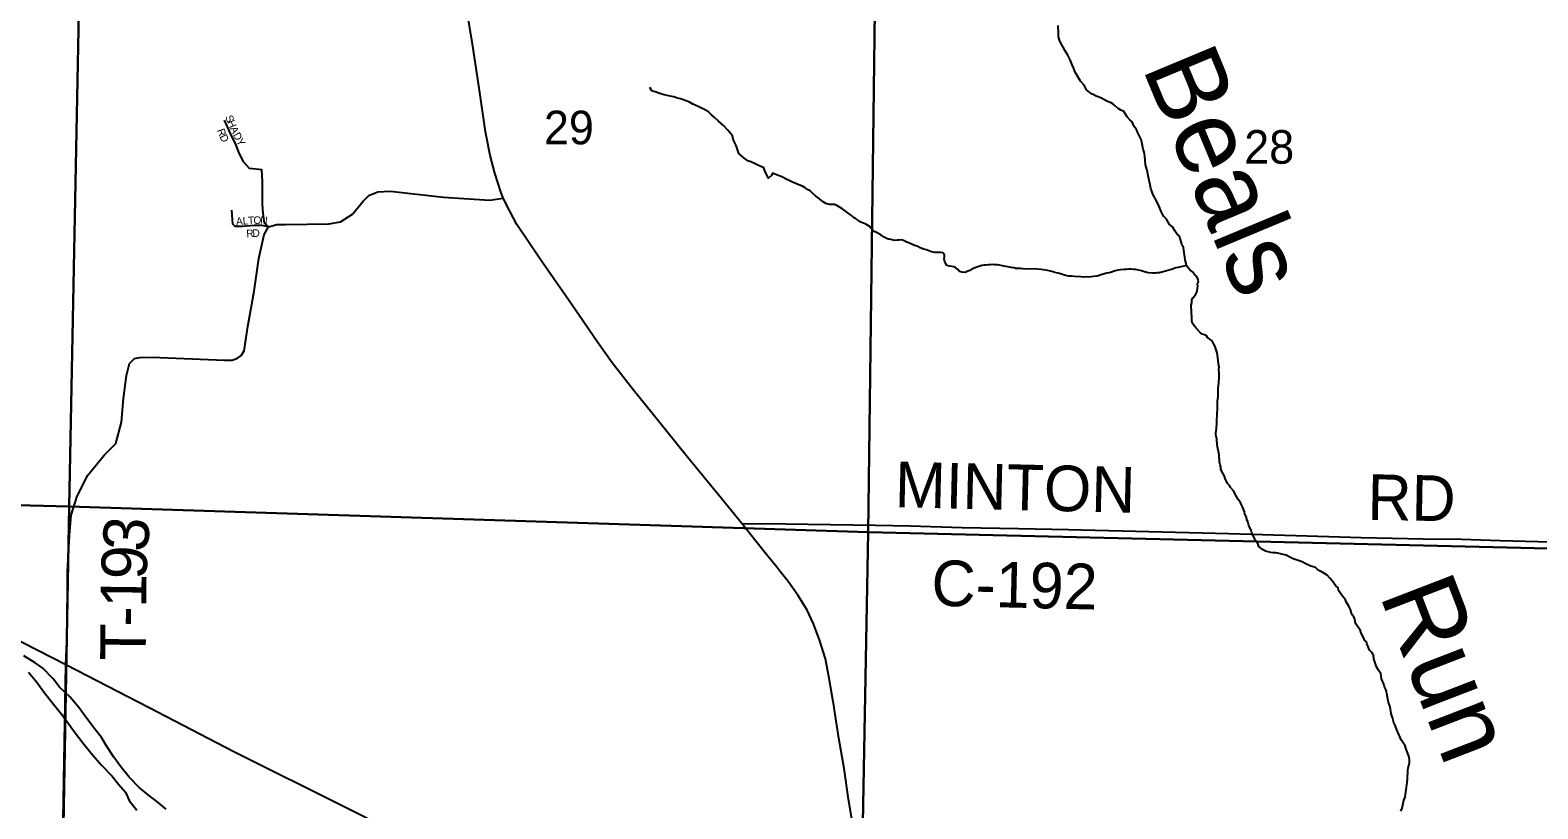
# Model space of a CAD drawing. Extents: x 1310247 to 1552180, y 377264 to 706493.
# Drawn here: x 1351371 to 1361294, y 517460 to 522581 of the extents above; entities that cross this region are included whole.
import ezdxf

# ---------------------------------------------------------------- set-up
doc = ezdxf.new("R2010")
doc.units = 0
for name, color, linetype in [('GM_X_County_Road', 7, 'Continuous'), ('GM_X_County_Road_Text', 7, 'Continuous'), ('GM_X_Major_River', 7, 'Continuous'), ('GM_X_Minor_River', 7, 'Continuous'), ('GM_X_Minor_River_Text', 7, 'Continuous'), ('GM_X_Section', 7, 'Continuous'), ('GM_X_Section_Text', 7, 'Continuous'), ('GM_X_Township_Road', 7, 'Continuous'), ('GM_X_Township_Road_Text', 7, 'Continuous'), ('GM_X_Township_ROW', 7, 'Continuous'), ('GM_X_Township_Subdivision', 7, 'Continuous'), ('GM_X_Township_Subdivision_Text', 7, 'Continuous'), ('GM_X_US_Route', 7, 'Continuous')]:
    doc.layers.add(name, color=color, linetype=linetype)

msp = doc.modelspace()

# ---------------------------------------------------------------- linework, layer by layer
at = {"layer": 'GM_X_County_Road'}
for points in [[(1346013, 519573.1), (1346145.6, 519582.5), (1346569.2, 519625.9), (1346757.2, 519637.8), (1347170.2, 519644.3), (1347850.3, 519648.3), (1348201.7, 519645.6), (1348388.2, 519652.2), (1348771, 519650.9), (1348902.6, 519649.6), (1349052.5, 519644.3), (1349156.4, 519623.3), (1349291.9, 519579.9), (1350325.7, 519064.3), (1350759.8, 518842), (1351606.8, 518409.2), (1352154, 518126.5), (1352711.7, 517837.1), (1353450.9, 517468.8), (1353963.9, 517211), (1354574.2, 516892.8), (1355459.2, 516399.3), (1355632.3, 516317.4)], [(1356055.9, 519335.9), (1356345.2, 519334.7), (1356933.6, 519324.6), (1357163.2, 519320.8), (1357505.1, 519309.8), (1357876, 519302.8), (1358204.4, 519296.4), (1358647, 519286.7), (1359260.9, 519270.5), (1359775, 519255.3), (1360130.2, 519243.3), (1360539, 519235.9), (1360791.7, 519233.5), (1361046.2, 519224.3), (1361377.9, 519216), (1361584.4, 519209.1), (1361598.1, 519209)]]:
    msp.add_lwpolyline(points, dxfattribs=at)
at = {"layer": 'GM_X_Major_River'}
for points in [[(1352266.8, 517458.2), (1352213.6, 517501.4), (1352148.4, 517552.9), (1352089.2, 517600.2), (1352022.4, 517667.8), (1351967.6, 517735.1), (1351922.9, 517800.2), (1351876.2, 517869.3), (1351841.3, 517928.2), (1351798.2, 517981.2), (1351743.6, 518054.6), (1351690.9, 518125.8), (1351634.1, 518193.2), (1351563.3, 518260.8), (1351522.3, 518313.8), (1351455.6, 518385.4), (1351404.1, 518420.5), (1351328.9, 518466.2)], [(1351360.7, 518359.2), (1351415.5, 518291.9), (1351466.2, 518222.7), (1351524.9, 518149.3), (1351579.6, 518080), (1351620.5, 518023), (1351673.2, 517951.7), (1351725.9, 517882.4), (1351772.9, 517825.3), (1351839.5, 517749.7), (1351910.2, 517674.1), (1351953.2, 517623), (1351998.3, 517570), (1352023.2, 517515.3), (1352074, 517450.1)]]:
    msp.add_lwpolyline(points, dxfattribs=at)
at = {"layer": 'GM_X_Minor_River'}
for points in [[(1358684.4, 521861.4), (1358670.9, 521887.8), (1358659.4, 521910.2), (1358651.7, 521926.4), (1358640.1, 521944.8), (1358628.5, 521965.1), (1358624.8, 521977.2), (1358609.1, 521991.7), (1358591.4, 522010.2), (1358570.1, 522044.8), (1358550.3, 522055.3), (1358532.5, 522065.8), (1358512.8, 522082.3), (1358497.1, 522096.8), (1358485.1, 522103.1), (1358461.3, 522111.7), (1358417.6, 522134.9), (1358387.8, 522147.6), (1358371.9, 522156.1), (1358356, 522162.5), (1358324.4, 522187.3), (1358307.1, 522219.8), (1358283.6, 522244.5), (1358256.6, 522293.3), (1358247, 522309.6), (1358239.3, 522327.9), (1358229.9, 522352.2), (1358216.6, 522384.6), (1358201.3, 522417.1), (1358183.8, 522445.6), (1358170.3, 522468), (1358160.6, 522484.3), (1358147.1, 522508.7), (1358139.8, 522537), (1358138.3, 522559.1), (1358137.5, 522611.2)], [(1357076.7, 521199.4), (1357062.6, 521197.8), (1357050.6, 521200.1), (1357036.6, 521204.4), (1357020.6, 521206.8), (1357006.7, 521211.2), (1356990.8, 521219.6), (1356969.1, 521234.2), (1356941.3, 521250.9), (1356925.4, 521257.3), (1356905.8, 521275.9), (1356894.1, 521292.2), (1356870.3, 521304.9), (1356838.5, 521317.7), (1356822.6, 521328.1), (1356802.9, 521342.6), (1356791, 521349), (1356777.2, 521361.3), (1356763.4, 521369.7), (1356743.7, 521386.2), (1356727.8, 521396.7), (1356714, 521407), (1356702.1, 521413.4), (1356680.4, 521428), (1356664.5, 521434.4), (1356634.4, 521435.1), (1356622.4, 521437.4), (1356608.4, 521441.8), (1356590.6, 521452.2), (1356568.9, 521468.8), (1356557, 521477.1), (1356539.3, 521491.6), (1356517.6, 521510.2), (1356503.9, 521524.6), (1356492, 521530.9), (1356472.2, 521543.5), (1356454.4, 521553.9), (1356440.4, 521558.3), (1356414.6, 521571), (1356388.7, 521581.6), (1356374.8, 521588), (1356362.9, 521594.3), (1356351, 521598.6), (1356319.2, 521615.5), (1356271.5, 521634.7), (1356257.6, 521641.1), (1356251.2, 521625.2), (1356230.7, 521607.6), (1356209.6, 521648.3), (1356200.1, 521674.6), (1356176.3, 521687.2), (1356164.4, 521691.5), (1356134.6, 521706.3), (1356114.7, 521714.8), (1356094.8, 521721.4), (1356069.2, 521742.1), (1356053.4, 521754.5), (1356035.7, 521769), (1356024.4, 521803.4), (1356016.8, 521821.6), (1356003.4, 521852), (1355997.7, 521864.2), (1355994.2, 521886.3), (1355962.9, 521923.2), (1355933.5, 521954.1), (1355902, 521982.9), (1355872.5, 522007.7), (1355854.8, 522024.2), (1355835.2, 522042.8), (1355821.3, 522053.1), (1355805.5, 522061.6), (1355793.5, 522065.9), (1355767.7, 522078.5), (1355747.8, 522087.1), (1355731.9, 522093.5), (1355714.1, 522104), (1355688.3, 522116.6), (1355664.4, 522125.3), (1355650.4, 522129.6), (1355624.5, 522136.3), (1355608.5, 522142.7), (1355594.5, 522145), (1355582.5, 522147.3), (1355564.6, 522151.8), (1355544.6, 522156.3), (1355528.6, 522158.7), (1355514.7, 522165.1), (1355502.7, 522169.4), (1355486.8, 522175.8), (1355474.8, 522178.1), (1355462.9, 522182.4), (1355449.3, 522202.8)], [(1359271.9, 519572.1), (1359266.1, 519584.3), (1359252.4, 519598.7), (1359235.1, 519631.2), (1359231.4, 519647.3), (1359219.9, 519667.7), (1359208.4, 519692), (1359206.7, 519706.1), (1359203.1, 519722.3), (1359199.5, 519742.4), (1359196.6, 519788.6), (1359193, 519808.8), (1359187.5, 519829), (1359184, 519853.1), (1359180.9, 519891.3), (1359177.3, 519911.4), (1359175.6, 519923.5), (1359176.2, 519947.6), (1359178.5, 519961.6), (1359181.3, 519997.6), (1359182.9, 520063.8), (1359185.4, 520085.8), (1359186.6, 520139.9), (1359189.4, 520171.9), (1359190.6, 520224), (1359193.1, 520244), (1359193.5, 520262.1), (1359196.3, 520298.1), (1359196.9, 520324.2), (1359195.5, 520350.3), (1359195.9, 520364.3), (1359192.4, 520386.5), (1359190.9, 520410.6), (1359184, 520458.9), (1359174.6, 520485.2), (1359170.9, 520501.3), (1359161.2, 520515.6), (1359151.7, 520537.9), (1359120.1, 520558.8), (1359114.3, 520570.9), (1359100.4, 520577.3), (1359084.4, 520581.7), (1359072.6, 520592), (1359045.2, 520620.8), (1359027.6, 520643.3), (1359019.9, 520655.5), (1359016.3, 520675.7), (1359013.8, 520739.9), (1359012.2, 520758), (1359012.5, 520772), (1359016.9, 520788), (1359017.4, 520808), (1359025.7, 520821.9), (1359040.2, 520839.6), (1359046.6, 520853.4), (1359052.9, 520865.3), (1359055.6, 520897.3), (1359053.9, 520911.4), (1359060.3, 520925.3), (1359058.6, 520939.4), (1359049.1, 520961.7), (1359035.3, 520974.1), (1359021.6, 520990.5), (1359005.9, 521002.9), (1358990.2, 521019.3), (1358982.5, 521033.6), (1358978.7, 521045.7), (1358973.3, 521069.9), (1358971.7, 521088), (1358964.7, 521134.3), (1358961.1, 521150.4), (1358953.4, 521164.7), (1358949.8, 521182.8), (1358942.2, 521203.1), (1358934.7, 521225.3), (1358919, 521241.8), (1358905.4, 521260.1), (1358889.9, 521286.6), (1358870.2, 521303.1), (1358851, 521337.7), (1358833.3, 521354.2), (1358823.6, 521370.5), (1358816, 521388.7), (1358800.7, 521421.2), (1358793.1, 521441.5), (1358779.6, 521463.9), (1358772, 521482.1), (1358760.4, 521502.5), (1358752.8, 521522.7), (1358747.2, 521538.9), (1358741.7, 521563.1), (1358729, 521621.6), (1358725.7, 521651.8), (1358712.6, 521694.2), (1358709.4, 521726.4), (1358707.9, 521750.5), (1358704.3, 521766.6), (1358702.5, 521778.7), (1358697, 521798.9), (1358688, 521843.3), (1358684.4, 521861.4)], [(1358982.5, 521033.6), (1358927.9, 521018.9), (1358911.8, 521017.3), (1358889.5, 521009.8), (1358828.9, 520991.3), (1358804.7, 520985.8), (1358786.5, 520984.3), (1358774.5, 520982.6), (1358760.4, 520982.9), (1358732.4, 520985.6), (1358720.4, 520987.9), (1358698.4, 520994.5), (1358684.5, 520998.9), (1358648.5, 521005.8), (1358636.5, 521006.1), (1358618.4, 521008.5), (1358602.4, 521008.9), (1358586.3, 521007.3), (1358568.2, 521005.8), (1358548.1, 521004.3), (1358532, 521002.7), (1358511.7, 520997.2), (1358487.5, 520989.7), (1358473.3, 520984.1), (1358457.2, 520982.5), (1358416.8, 520971.5), (1358402.6, 520965.8), (1358390.5, 520962.1), (1358370.3, 520960.6), (1358354.2, 520959), (1358340.1, 520957.3), (1358328.1, 520957.6), (1358304, 520956.2), (1358286, 520958.6), (1358243.8, 520959.7), (1358223.8, 520962.2), (1358205.7, 520962.7), (1358177.8, 520969.4), (1358145.9, 520980.2), (1358133.9, 520982.5), (1358115.9, 520987), (1358104, 520991.3), (1358068.1, 521000.2), (1358026, 521007.3), (1357979.9, 521010.4), (1357937.7, 521009.5), (1357905.6, 521010.3), (1357889.6, 521012.7), (1357857.5, 521013.5), (1357845.6, 521017.8), (1357827.5, 521020.2), (1357805.6, 521024.8), (1357793.6, 521027.1), (1357771.6, 521031.6), (1357751.6, 521034.2), (1357737.6, 521036.5), (1357717.5, 521037), (1357705.5, 521039.3), (1357691.4, 521037.7), (1357679.4, 521038), (1357663.2, 521034.4), (1357649.2, 521034.7), (1357635.1, 521033), (1357614.8, 521025.5), (1357600.7, 521021.9), (1357584.5, 521016.3), (1357568.2, 521008.6), (1357556, 521000.9), (1357541.8, 520995.3), (1357525.6, 520987.6), (1357503.5, 520988.2), (1357487.6, 520994.6), (1357475.8, 521006.9), (1357464, 521017.2), (1357450.1, 521023.6), (1357438.1, 521025.9), (1357424.1, 521028.3), (1357404.1, 521032.8), (1357398.4, 521045), (1357390.7, 521057.2), (1357387.1, 521077.3), (1357389.4, 521089.3), (1357389.7, 521103.4), (1357378, 521115.7), (1357364, 521118), (1357325.8, 521119), (1357313.8, 521121.3), (1357297.9, 521125.7), (1357285.9, 521130), (1357270, 521136.4), (1357250, 521140.9), (1357224.2, 521151.6), (1357208.3, 521160), (1357192.3, 521164.5), (1357158.5, 521179.3), (1357140.6, 521185.8), (1357118.8, 521196.4), (1357102.8, 521200.8), (1357090.7, 521199.1), (1357076.7, 521199.4)], [(1360436.2, 517657.7), (1360437.5, 517711.8), (1360439.9, 517727.8), (1360448.7, 517763.6), (1360449.1, 517779.7), (1360447.6, 517799.8), (1360441.8, 517812), (1360426.7, 517852.5), (1360421.2, 517874.6), (1360394, 517913.5), (1360365.4, 517980.3), (1360358, 518004.6), (1360348.2, 518016.9), (1360342.8, 518043.1), (1360339, 518055.2), (1360333.4, 518071.4), (1360329.8, 518087.5), (1360322.7, 518129.8), (1360317, 518142), (1360311.4, 518160.2), (1360305.8, 518180.4), (1360300.7, 518218.6), (1360296.9, 518230.8), (1360293.3, 518244.9), (1360285.6, 518263.1), (1360280, 518279.3), (1360264.8, 518315.8), (1360259.6, 518350), (1360246, 518372.4), (1360232.4, 518392.8), (1360223, 518419.1), (1360215.6, 518447.4), (1360212.1, 518469.6), (1360202.5, 518487.8), (1360186.8, 518504.3), (1360167.7, 518546.9), (1360166, 518559), (1360154.2, 518569.3), (1360148.5, 518581.5), (1360131.2, 518616), (1360125.6, 518636.2), (1360113.9, 518650.5), (1360104.2, 518662.8), (1360096.5, 518677), (1360092.8, 518691.2), (1360089.1, 518707.3), (1360083.4, 518721.5), (1360073.7, 518733.8), (1360067.9, 518745.9), (1360060.5, 518770.2), (1360050.9, 518792.5), (1360031.5, 518821.1), (1360027.8, 518835.2), (1360008.3, 518857.8), (1359983.1, 518896.5), (1359979.4, 518912.6), (1359961.7, 518929.1), (1359952, 518943.4), (1359940.4, 518959.7), (1359924.7, 518976.2), (1359907.1, 518996.7), (1359889.3, 519007.1), (1359863.5, 519021.8), (1359849.6, 519028.2), (1359829.9, 519046.7), (1359800, 519055.5), (1359772.2, 519068.2), (1359758.3, 519074.6), (1359742.5, 519085), (1359716.6, 519093.7), (1359682.7, 519104.5), (1359660.9, 519115.1), (1359637.1, 519127.8), (1359617.1, 519132.3), (1359601.1, 519136.7), (1359583.1, 519141.1), (1359569.1, 519143.5), (1359553.1, 519143.9), (1359537.1, 519146.3), (1359501.1, 519155.2), (1359481.3, 519165.7), (1359457.6, 519184.4), (1359454, 519198.5), (1359436.5, 519225), (1359423.1, 519253.4), (1359411.6, 519275.8), (1359407.9, 519291.9), (1359398.3, 519308.2), (1359392.6, 519322.4), (1359385.2, 519348.6), (1359379.4, 519360.8), (1359375.7, 519375), (1359366.3, 519399.3), (1359362.6, 519413.4), (1359353.2, 519441.7), (1359343.6, 519460), (1359337.9, 519474.2), (1359322.3, 519494.6), (1359310.7, 519513), (1359291.5, 519551.6), (1359271.9, 519572.1)], [(1360393.1, 517444.1), (1360401.6, 517464), (1360410.7, 517507.9), (1360415, 517521.8), (1360421.4, 517537.7), (1360423.8, 517553.7), (1360428.9, 517601.7), (1360431.3, 517615.7), (1360433.7, 517633.7), (1360436.2, 517657.7)]]:
    msp.add_lwpolyline(points, dxfattribs=at)
at = {"layer": 'GM_X_Section'}
for points in [[(1351732.1, 524716), (1351628.4, 519447.7), (1345981.1, 519592.5), (1346105.1, 524794.3)], [(1356953.9, 524597.4), (1356887, 519278.3), (1351628.4, 519447.7), (1351732.1, 524716)], [(1362206.1, 524496.1), (1362094.6, 519154.1), (1356887, 519278.3), (1356953.9, 524597.4)], [(1345981.1, 519592.5), (1351628.4, 519447.7), (1351534.1, 514153.2), (1351212.3, 514163), (1345868.1, 514272.4)], [(1356887, 519278.3), (1356789.5, 514019.9), (1355308.3, 514059.8), (1351534.1, 514153.2), (1351628.4, 519447.7)], [(1362094.6, 519154.1), (1362023, 513887.1), (1360737.5, 513916.3), (1356789.5, 514019.9), (1356887, 519278.3)]]:
    msp.add_lwpolyline(points, close=True, dxfattribs=at)
at = {"layer": 'GM_X_Township_Road'}
for points in [[(1351606.8, 518409.2), (1351614.2, 518610.1), (1351617.3, 519017.7), (1351630.3, 519258.2), (1351641.4, 519392.2), (1351679.9, 519516), (1351750.9, 519654.7), (1351858.5, 519785.9), (1351936, 519861.6), (1351971.5, 520003.8), (1351986.4, 520159.3), (1352004.6, 520308.8), (1352024.2, 520389.3), (1352058.7, 520420.4), (1352092.6, 520428.6), (1352175.1, 520430.6), (1352651.3, 520411), (1352700, 520409.6), (1352735.2, 520423.1), (1352759.5, 520440.7), (1352779.2, 520472.5), (1352804.2, 520631.5), (1352846.1, 520864.2), (1352877.2, 521078), (1352911.1, 521236.9), (1352938.8, 521286.3), (1352994.3, 521302.5), (1353053.8, 521302.5), (1353336.6, 521307.9), (1353413.7, 521320.1), (1353492.1, 521370.2), (1353563.9, 521455.4), (1353600.4, 521493.3), (1353603.6, 521494.6)], [(1353603.6, 521494.6), (1353659.9, 521517.6), (1353741.1, 521521.7), (1354091.5, 521482.5), (1354224.7, 521473.6)], [(1354224.7, 521473.6), (1354395.9, 521462.2), (1354484.9, 521476.4)]]:
    msp.add_lwpolyline(points, dxfattribs=at)
at = {"layer": 'GM_X_Township_ROW'}
msp.add_lwpolyline([(1351530, 514137.1), (1351530.7, 514155.7), (1351533.2, 514264), (1351534.8, 514333.6), (1351606.8, 518409.2)], dxfattribs=at)
at = {"layer": 'GM_X_Township_Subdivision'}
for points in [[(1352938.8, 521286.3), (1352914.5, 521310.6), (1352905, 521376.9), (1352900.9, 521436.5), (1352900.9, 521585.3), (1352895.5, 521662.4), (1352815.7, 521671.9), (1352775.1, 521715.2), (1352744, 521777.4), (1352726.4, 521824.7), (1352689.9, 521901.9), (1352650.5, 521989.1)], [(1352938.8, 521286.3), (1352896.2, 521295.8), (1352848.8, 521297.1), (1352769, 521290.4), (1352721, 521290.4), (1352704.1, 521304.6), (1352698.7, 521396.6)]]:
    msp.add_lwpolyline(points, dxfattribs=at)
at = {"layer": 'GM_X_US_Route'}
for points in [[(1354372.9, 521890), (1354368.9, 521911), (1354331.8, 522170.1), (1354285.2, 522474.7), (1354232.4, 522794.5)], [(1354822.6, 520938.9), (1354812.9, 520952.9), (1354744.1, 521052.2), (1354659.8, 521176), (1354575, 521302.5), (1354522.8, 521398.2), (1354484.9, 521476.4), (1354469.4, 521517.1), (1354430, 521640.4), (1354398.4, 521755.4), (1354372.9, 521890)], [(1356284.5, 519048.2), (1356205.6, 519144.9), (1356055.9, 519335.9), (1355898.9, 519526.9), (1355698, 519771.7), (1355461.9, 520063.2), (1355342.7, 520212.5), (1355201.5, 520392.5), (1355105.3, 520528), (1354987.6, 520701.4), (1354875, 520863.4), (1354822.6, 520938.9)], [(1356660.3, 518142.5), (1356654.7, 518176.1), (1356627.8, 518330.5), (1356606.6, 518445.5), (1356567.3, 518571.6), (1356526.7, 518676), (1356481.9, 518769.8), (1356423.7, 518864.9), (1356359, 518955), (1356298, 519031.7), (1356284.5, 519048.2)], [(1356997.4, 515963.4), (1356990, 516008.4), (1356982.7, 516055.6), (1356972.5, 516121.8), (1356952, 516267.3), (1356921.9, 516470.7), (1356879.7, 516752.4), (1356837.2, 517018.1), (1356795.8, 517289.1), (1356757.4, 517523.1), (1356727.7, 517724.1), (1356693.6, 517924.6), (1356665.9, 518109), (1356660.3, 518142.5)]]:
    msp.add_lwpolyline(points, dxfattribs=at)

# ---------------------------------------------------------------- texts
at = {"layer": 'GM_X_County_Road_Text'}
for s, rotation, p in [('MINTON', 358.63656, (1357059.7, 519444)), ('RD', 359.0109, (1360170.9, 519360.4)), ('C-192', 358.63055, (1357300.5, 518796.2))]:
    msp.add_text(s, height=300, rotation=rotation, dxfattribs=at).set_placement(p)
at = {"layer": 'GM_X_Minor_River_Text'}
for s, height, rotation, p in [('Beals', 500, 292.64522, (1358687.2, 522335.2)), ('Run', 499.95, 291.06072, (1360249.2, 518870))]:
    msp.add_text(s, height=height, rotation=rotation, dxfattribs=at).set_placement(p)
at = {"layer": 'GM_X_Section_Text'}
for s, p in [('29', (1354752.5, 521830)), ('28', (1359361.5, 521702.4))]:
    msp.add_text(s, height=221, rotation=0.00001, dxfattribs=at).set_placement(p)
at = {"layer": 'GM_X_Township_Road_Text'}
for s, rotation, p in [('3', 85.22122, (1352143.6, 519144.4)), ('9', 87.78909, (1352136.7, 518963.2)), ('1', 89.25449, (1352134.4, 518780.5)), ('-', 89.50042, (1352133.3, 518657.6)), ('T', 89.55964, (1352131.6, 518433.3))]:
    msp.add_text(s, height=300, rotation=rotation, dxfattribs=at).set_placement(p)
at = {"layer": 'GM_X_Township_Subdivision_Text'}
for s, rotation, p in [('S', 292.68291, (1352653.6, 522009.3)), ('H', 292.69156, (1352667.1, 521976.8)), ('R', 290.62995, (1352600.2, 521922.4)), ('D', 296.41879, (1352616.3, 521880.4)), ('A', 294.46777, (1352684.8, 521934.6)), ('D', 297.46186, (1352704.3, 521892)), ('Y', 299.21137, (1352725.3, 521851.5)), ('A', 4.09068, (1352727.7, 521297.8)), ('L', 4.07442, (1352771.6, 521301)), ('T', 4.06829, (1352806.7, 521303.5)), ('O', 0.52458, (1352841, 521305.9)), ('N', 356.47888, (1352884.1, 521306.4)), ('R', 4.10768, (1352795.8, 521217.4)), ('D', 1.68324, (1352834.7, 521220.2))]:
    msp.add_text(s, height=50, rotation=rotation, dxfattribs=at).set_placement(p)

doc.saveas('drawing.dxf')
